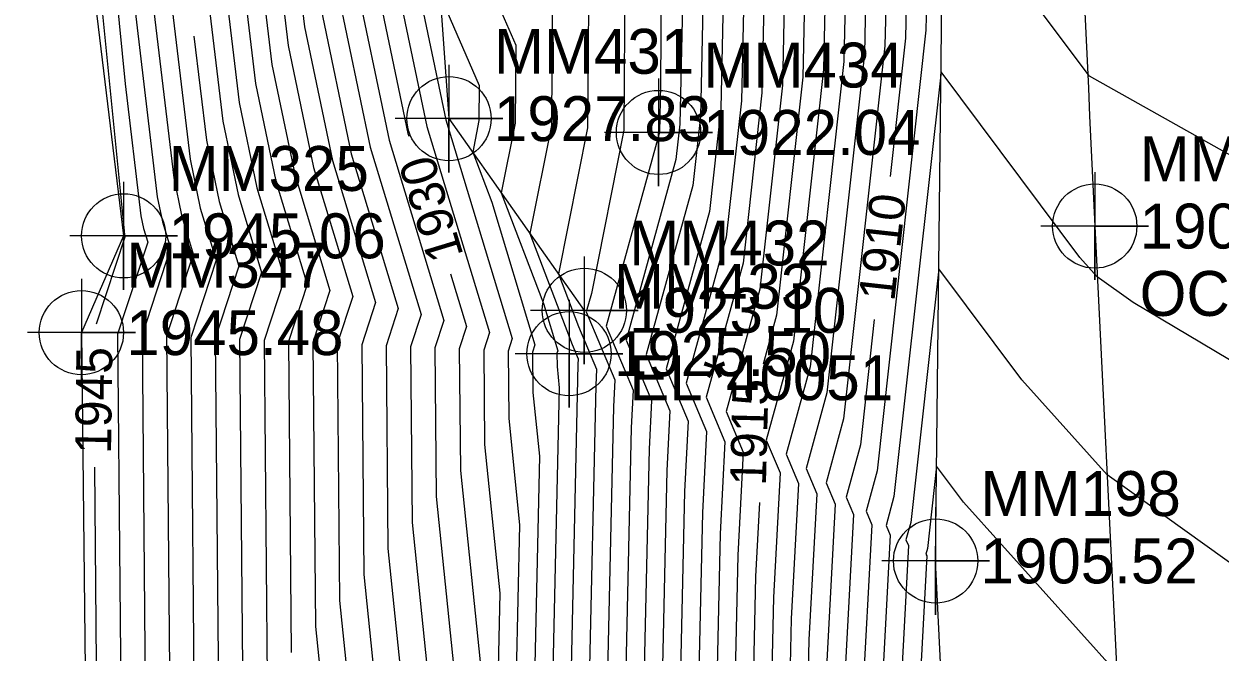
# Model space of a CAD drawing. Extents: x 1004378 to 1005103, y 553854 to 554288.
# Drawn here: x 1004943.2 to 1005009.8, y 554030.8 to 554065.8 of the extents above; entities that cross this region are included whole.
import ezdxf

# ---------------------------------------------------------------- set-up
doc = ezdxf.new("R2010")
doc.units = 0
for name, color, linetype in [('DTM Contours Major', 7, 'Continuous'), ('DTM Contours Major Text', 7, 'Continuous'), ('DTM Contours Minor', 7, 'Continuous'), ('Exist DTM Breakline', 7, 'Continuous'), ('Exist DTM Breakline Cogo Comment', 7, 'Continuous'), ('Exist DTM Breakline Cogo Elevation', 7, 'Continuous'), ('Exist DTM Breakline Cogo Number', 7, 'Continuous'), ('Exist DTM Breakline Cogo Point CELL', 7, 'Continuous'), ('Exist DTM Regular Point CELL', 7, 'Continuous'), ('Exist DTM Regular Point Cogo Elevation', 7, 'Continuous'), ('Exist DTM Regular Point Cogo Number', 7, 'Continuous'), ('Exist Roads EOP', 7, 'Continuous'), ('Exist Roads EOP Cogo Comment', 7, 'Continuous'), ('Exist Roads EOP Cogo Elevation', 7, 'Continuous'), ('Exist Roads EOP Cogo Number', 7, 'Continuous'), ('Exist Roads EOP Cogo Point CELL', 7, 'Continuous')]:
    doc.layers.add(name, color=color, linetype=linetype)

msp = doc.modelspace()

# ---------------------------------------------------------------- linework, layer by layer
at = {"layer": 'DTM Contours Major'}
for points in [[(1004974.291, 554156.941), (1004974.539, 554153.633), (1004973.275, 554148.595), (1004975.533, 554125.683), (1004973.303, 554118.045), (1004966.649, 554100.709), (1004964.833, 554091.127), (1004964.446, 554090.268), (1004962.705, 554079.148), (1004961.826, 554075.049), (1004962.449, 554069.829), (1004964.566, 554059.674), (1004964.614, 554059.515)], [(1005000.387, 554132.231), (1004993.714, 554134.749), (1004991.768, 554134.399), (1004990.994, 554131.312), (1004991.049, 554130.756), (1004984.364, 554107.86), (1004983.427, 554105.42), (1004981.8, 554096.829), (1004980.532, 554086.898), (1004982.359, 554084.869), (1004986.035, 554077.591), (1004986.969, 554072.114), (1004986.697, 554069.843), (1004986.544, 554062.802), (1004985.079, 554049.563), (1004984.328, 554046.826)], [(1004912.064, 554126.115), (1004911.158, 554121.47), (1004914.724, 554118.563), (1004927.833, 554107.862), (1004928.535, 554107.974), (1004932.097, 554104.869), (1004931.879, 554104.636), (1004950.839, 554094.361), (1004950.581, 554093.249), (1004946.204, 554080.072), (1004948.75, 554054.444), (1004948.799, 554054.036), (1004948.807, 554053.997), (1004948.82, 554053.955), (1004947.217, 554049.061)], [(1004962.871, 554103.868), (1004961.056, 554099.139), (1004960.026, 554093.701), (1004959.475, 554092.482), (1004958.495, 554086.221), (1004956.453, 554076.695), (1004957.899, 554064.565), (1004959.313, 554057.782), (1004961.493, 554050.599), (1004960.632, 554047.97), (1004960.758, 554033.678), (1004963.076, 554011.188), (1004962.949, 554005.526)], [(1004970.528, 554093.236), (1004969.641, 554088.552), (1004969.416, 554088.055), (1004967.45, 554075.492), (1004969.542, 554073.85), (1004972.596, 554066.826), (1004972.547, 554060.122), (1004971.354, 554054.113), (1004973.706, 554047.918), (1004974.042, 554047.122), (1004974.026, 554046.818), (1004973.213, 554010.493), (1004972.706, 553999.94), (1004972.315, 553996.671), (1004972.236, 553995.839)], [(1004974.172, 554084.471), (1004973.846, 554082.386), (1004977.708, 554079.356), (1004979.951, 554076.865), (1004980.929, 554074.931), (1004981.177, 554073.474), (1004981.105, 554072.871), (1004980.838, 554060.621), (1004980.413, 554056.78), (1004977.827, 554047.365), (1004979.146, 554044.236), (1004978.97, 554040.918), (1004978.353, 554013.324), (1004977.634, 553998.359), (1004977.079, 553993.724), (1004976.557, 553988.222)], [(1005051.433, 554076.836), (1005050.379, 554076.997), (1005049.638, 554077.419), (1005048.654, 554073.906), (1005043.562, 554064.845), (1005040.05, 554064.129), (1005027.148, 554065.55), (1005021.967, 554066.02), (1005015.22, 554068.538), (1005006.107, 554071.836), (1005002.083, 554074.095), (1005000.368, 554076.389), (1005000.016, 554076.907), (1004996.136, 554080.152), (1004993.696, 554082.636), (1004992.74, 554083.442), (1004991.884, 554081.943), (1004990.65, 554081.337), (1004990.87, 554080.789), (1004991.142, 554080.251), (1004992.761, 554070.753), (1004992.29, 554066.815), (1004992.25, 554064.983), (1004991.398, 554057.275)], [(1004952.659, 554065.091), (1004953.349, 554059.3), (1004954.06, 554055.889), (1004955.156, 554052.277), (1004953.842, 554048.264), (1004954.035, 554026.446), (1004955.827, 554009.057), (1004955.839, 554007.597), (1004955.608, 554000.346), (1004953.019, 553984.313), (1004948.054, 553966.564)], [(1004966.938, 554051.86), (1004967.829, 554048.921), (1004967.422, 554047.677), (1004967.482, 554040.91), (1004968.579, 554030.261), (1004968.073, 554007.661), (1004967.778, 554001.521), (1004967.551, 553999.619), (1004964.757, 553970.225), (1004964.471, 553967.778), (1004960.654, 553952.767)], [(1004990.518, 554049.324), (1004989.746, 554042.345), (1004988.945, 554039.431), (1004989.353, 554038.463), (1004988.859, 554029.118), (1004988.632, 554018.987), (1004987.49, 553995.198), (1004986.608, 553987.828), (1004985.684, 553978.101), (1004983.38, 553958.418), (1004981.497, 553951.011), (1004981.379, 553950.073)], [(1004947.118, 554041.088), (1004947.311, 554019.215), (1004947.454, 554017.827), (1004947.487, 554013.967), (1004946.931, 553996.538), (1004946.571, 553995.053), (1004931.009, 553978.241), (1004928.196, 553974.545), (1004916.189, 553970.124), (1004914.888, 553969.412), (1004912.358, 553969.149), (1004911.765, 553968.617), (1004911.067, 553969.318), (1004903.448, 553970.699)], [(1004984.132, 554039.131), (1004983.915, 554035.018), (1004983.493, 554016.156), (1004982.562, 553996.779), (1004981.844, 553990.776), (1004980.452, 553976.132), (1004978.652, 553960.758), (1004976.062, 553950.567), (1004975.294, 553944.427), (1004974.577, 553939.804)]]:
    msp.add_lwpolyline(points, dxfattribs=at)
at = {"layer": 'DTM Contours Minor'}
for points in [[(1004988.98, 554130.079), (1004982.889, 554109.218), (1004981.19, 554104.792), (1004978.237, 554089.207), (1004977.787, 554085.675), (1004981.396, 554081.667), (1004983.993, 554076.527), (1004984.652, 554072.658), (1004984.46, 554071.054), (1004984.262, 554061.93), (1004983.213, 554052.45), (1004981.163, 554044.985), (1004982.208, 554042.504), (1004981.937, 554037.378), (1004981.437, 554015.023)], [(1004990.014, 554130.417), (1004983.627, 554108.539), (1004982.309, 554105.106), (1004980.019, 554093.018), (1004979.159, 554086.286), (1004981.877, 554083.268), (1004985.014, 554077.059), (1004985.811, 554072.386), (1004985.579, 554070.449), (1004985.403, 554062.366), (1004984.146, 554051.006), (1004982.275, 554044.191), (1004983.229, 554041.926), (1004982.926, 554036.198), (1004982.465, 554015.589)], [(1004986.911, 554129.403), (1004981.414, 554110.576), (1004978.953, 554104.164), (1004975.41, 554085.463), (1004975.381, 554085.398), (1004975.125, 554083.765), (1004976.951, 554082.333), (1004980.433, 554078.466), (1004981.95, 554075.463), (1004982.335, 554073.202), (1004982.223, 554072.265), (1004981.979, 554061.057), (1004981.346, 554055.337), (1004978.939, 554046.571), (1004980.166, 554043.658), (1004979.959, 554039.738), (1004979.381, 554013.891)], [(1004987.946, 554129.741), (1004982.152, 554109.897), (1004980.072, 554104.478), (1004976.456, 554085.395), (1004976.414, 554085.064), (1004980.914, 554080.067), (1004982.971, 554075.995), (1004983.494, 554072.93), (1004983.342, 554071.66), (1004983.12, 554061.493), (1004982.279, 554053.893), (1004980.051, 554045.778), (1004981.187, 554043.081), (1004980.948, 554038.558), (1004980.409, 554014.457)], [(1004983.808, 554128.388), (1004979.202, 554112.613), (1004975.597, 554103.222), (1004972.525, 554087.008), (1004972.399, 554086.726), (1004971.288, 554079.628), (1004978.513, 554073.96), (1004978.694, 554073.543), (1004978.613, 554062.384), (1004978.555, 554059.749), (1004978.546, 554059.667), (1004975.604, 554048.951), (1004977.104, 554045.39), (1004976.992, 554043.278), (1004976.297, 554012.192)], [(1004984.843, 554128.727), (1004979.94, 554111.934), (1004976.716, 554103.536), (1004973.487, 554086.493), (1004973.393, 554086.284), (1004972.567, 554081.007), (1004978.466, 554076.38), (1004979.47, 554075.265), (1004979.907, 554074.399), (1004980.018, 554073.747), (1004979.986, 554073.476), (1004979.696, 554060.185), (1004979.479, 554058.224), (1004976.716, 554048.158), (1004978.125, 554044.813), (1004977.981, 554042.098), (1004977.325, 554012.758)], [(1004981.739, 554127.712), (1004977.727, 554113.971), (1004973.36, 554102.594), (1004970.602, 554088.037), (1004970.41, 554087.612), (1004968.729, 554076.871), (1004972.533, 554073.887), (1004974.629, 554069.065), (1004974.562, 554059.989), (1004972.947, 554051.855), (1004974.061, 554048.923), (1004975.063, 554046.545), (1004975.015, 554045.638), (1004974.241, 554011.059)], [(1004982.774, 554128.05), (1004978.465, 554113.292), (1004974.479, 554102.908), (1004971.564, 554087.523), (1004971.404, 554087.169), (1004970.008, 554078.249), (1004975.523, 554073.924), (1004976.661, 554071.304), (1004976.578, 554059.857), (1004974.774, 554050.773), (1004974.492, 554049.745), (1004976.083, 554045.967), (1004976.003, 554044.458), (1004975.269, 554011.625)], [(1004979.671, 554127.036), (1004976.253, 554115.329), (1004971.123, 554101.966), (1004968.679, 554089.067), (1004968.422, 554088.497), (1004966.171, 554074.113), (1004966.552, 554073.814), (1004970.563, 554064.587), (1004970.531, 554060.254), (1004969.76, 554056.371), (1004972.101, 554050.208), (1004972.899, 554047.579), (1004972.854, 554047.442), (1004972.86, 554046.695), (1004972.981, 554045.52), (1004972.185, 554009.926)], [(1004977.602, 554126.359), (1004974.778, 554116.687), (1004968.886, 554101.338), (1004966.756, 554090.097), (1004966.434, 554089.383), (1004964.389, 554076.319), (1004963.976, 554074.391), (1004964.268, 554071.934), (1004966.667, 554060.431), (1004970.364, 554048.25), (1004970.138, 554047.559), (1004970.171, 554043.802), (1004970.78, 554037.89), (1004970.129, 554008.794)], [(1004978.636, 554126.697), (1004975.515, 554116.008), (1004970.004, 554101.652), (1004967.718, 554089.582), (1004967.428, 554088.94), (1004965.231, 554074.905), (1004965.05, 554074.061), (1004965.178, 554072.987), (1004966.353, 554067.357), (1004968.53, 554062.348), (1004968.516, 554060.387), (1004968.167, 554058.63), (1004969.226, 554055.84), (1004971.631, 554047.915), (1004971.496, 554047.501), (1004971.516, 554045.249), (1004971.881, 554041.705), (1004971.157, 554009.36)], [(1005041.535, 554126.294), (1005027.186, 554113.002), (1005025.646, 554112.306), (1005019.626, 554109.515), (1005013.669, 554108.071), (1005006.504, 554108.468), (1005001.004, 554108.005), (1004994.526, 554114.001), (1004990.716, 554115.591), (1004987.329, 554111.605), (1004985.839, 554106.502), (1004985.665, 554106.048), (1004985.362, 554104.451), (1004983.277, 554088.12), (1004983.322, 554088.07), (1004988.078, 554078.655), (1004989.286, 554071.569), (1004988.935, 554068.632), (1004988.827, 554063.674), (1004986.946, 554046.675), (1004985.61, 554041.811), (1004986.291, 554040.195), (1004985.892, 554032.658), (1004985.548, 554017.288)], [(1004976.568, 554126.021), (1004974.041, 554117.366), (1004967.767, 554101.024), (1004965.795, 554090.612), (1004965.44, 554089.826), (1004963.547, 554077.734), (1004962.901, 554074.72), (1004963.358, 554070.882), (1004965.617, 554060.053), (1004969.097, 554048.586), (1004968.78, 554047.618), (1004968.826, 554042.356), (1004969.679, 554034.076), (1004969.101, 554008.227)], [(1004935.046, 554124.799), (1004945.367, 554115.802), (1004966.063, 554119.983), (1004957.7, 554098.197), (1004957.141, 554095.246), (1004956.493, 554093.81), (1004955.969, 554090.464), (1004953.229, 554077.683), (1004955.169, 554061.406), (1004956.161, 554056.646), (1004957.691, 554051.606), (1004956.558, 554048.146), (1004956.724, 554029.339)], [(1004973.465, 554125.006), (1004971.828, 554119.403), (1004964.412, 554100.081), (1004962.91, 554092.157), (1004962.458, 554091.154), (1004961.021, 554081.977), (1004959.677, 554075.708), (1004960.629, 554067.723), (1004962.465, 554058.917), (1004965.295, 554049.592), (1004964.706, 554047.794), (1004964.792, 554038.017), (1004966.378, 554022.632)], [(1004974.499, 554125.345), (1004972.566, 554118.724), (1004965.53, 554100.395), (1004963.872, 554091.642), (1004963.452, 554090.711), (1004961.863, 554080.563), (1004960.752, 554075.378), (1004961.539, 554068.776), (1004963.515, 554059.296), (1004966.562, 554049.257), (1004966.064, 554047.735), (1004966.137, 554039.463), (1004967.478, 554026.447)], [(1004989.854, 554123.457), (1004985.101, 554107.181), (1004984.546, 554105.734), (1004983.581, 554100.64), (1004981.905, 554087.509), (1004982.841, 554086.469), (1004987.056, 554078.123), (1004988.127, 554071.842), (1004987.816, 554069.238), (1004987.685, 554063.238), (1004986.012, 554048.119), (1004984.498, 554042.605), (1004985.27, 554040.772), (1004984.903, 554033.838), (1004984.52, 554016.722)], [(1004919.981, 554122.802), (1004927.333, 554116.8), (1004932.255, 554117.588), (1004952.404, 554100.025), (1004955.66, 554100.683), (1004954.344, 554097.255), (1004954.256, 554096.791), (1004953.511, 554095.139), (1004953.443, 554094.708), (1004950.005, 554078.671), (1004952.439, 554058.248), (1004953.009, 554055.511), (1004953.889, 554052.612), (1004952.484, 554048.322), (1004952.69, 554025)], [(1004968.142, 554122.798), (1004958.819, 554098.511), (1004958.102, 554094.731), (1004957.487, 554093.368), (1004956.811, 554089.05), (1004954.303, 554077.354), (1004956.079, 554062.459), (1004957.212, 554057.025), (1004958.958, 554051.27), (1004957.916, 554048.088), (1004958.069, 554030.785)], [(1004934.115, 554122.395), (1004947.713, 554110.543), (1004962.595, 554113.55), (1004956.581, 554097.883), (1004956.179, 554095.761), (1004955.499, 554094.253), (1004955.127, 554091.879), (1004952.154, 554078.013), (1004954.259, 554060.353), (1004955.111, 554056.268), (1004956.424, 554051.941), (1004955.2, 554048.205), (1004955.379, 554027.893)], [(1004968.879, 554122.119), (1004959.937, 554098.825), (1004959.064, 554094.216), (1004958.481, 554092.925), (1004957.653, 554087.635), (1004955.378, 554077.025), (1004956.989, 554063.512), (1004958.262, 554057.403), (1004960.226, 554050.935), (1004959.274, 554048.029), (1004959.413, 554032.232), (1004961.975, 554007.374)], [(1004918.667, 554121.742), (1004927.458, 554114.566), (1004931.325, 554115.185), (1004950.953, 554098.075), (1004949.754, 554096.79), (1004952.721, 554095.183), (1004949.04, 554079.301), (1004948.941, 554079.002), (1004948.999, 554078.42), (1004951.529, 554057.195), (1004951.959, 554055.132), (1004952.622, 554052.948), (1004951.126, 554048.381), (1004951.345, 554023.554)], [(1004970.354, 554120.761), (1004962.174, 554099.453), (1004960.987, 554093.186), (1004960.469, 554092.039), (1004959.337, 554084.806), (1004957.527, 554076.366), (1004958.809, 554065.617), (1004960.364, 554058.16), (1004962.76, 554050.264), (1004961.99, 554047.911), (1004962.103, 554035.124), (1004964.176, 554015.003)], [(1004917.352, 554120.683), (1004927.583, 554112.331), (1004930.395, 554112.781), (1004944.668, 554100.34), (1004943.796, 554099.406), (1004952.093, 554094.909), (1004949.554, 554083.951), (1004948.029, 554079.359), (1004948.916, 554070.428), (1004950.619, 554056.142), (1004950.908, 554054.754), (1004951.354, 554053.283), (1004949.768, 554048.44), (1004950.001, 554022.107)], [(1004971.091, 554120.082), (1004963.293, 554099.767), (1004961.949, 554092.671), (1004961.463, 554091.597), (1004960.179, 554083.392), (1004958.602, 554076.037), (1004959.719, 554066.67), (1004961.414, 554058.539), (1004964.027, 554049.928), (1004963.348, 554047.853), (1004963.448, 554036.571), (1004965.277, 554018.817)], [(1004916.038, 554119.623), (1004927.708, 554110.097), (1004929.465, 554110.378), (1004938.382, 554102.604), (1004937.837, 554102.021), (1004951.466, 554094.635), (1004950.068, 554088.6), (1004947.116, 554079.715), (1004948.833, 554062.436), (1004949.709, 554055.089), (1004949.858, 554054.375), (1004950.087, 554053.619), (1004948.41, 554048.498), (1004948.656, 554020.661)], [(1005010.132, 554096.182), (1005001.278, 554096.56), (1004999.274, 554098.601), (1004990.276, 554106.187), (1004990.27, 554106.177), (1004986.161, 554098.879), (1004984.854, 554088.057), (1004985.769, 554085.78), (1004989.099, 554079.187), (1004990.444, 554071.297), (1004990.053, 554068.027), (1004989.968, 554064.111), (1004987.879, 554045.232), (1004986.722, 554041.018), (1004987.312, 554039.617), (1004986.881, 554031.478), (1004986.576, 554017.855)], [(1005014.682, 554081.634), (1005004.85, 554085.192), (1005001.681, 554085.328), (1004996.485, 554090.618), (1004991.508, 554094.815), (1004987.057, 554087.013), (1004986.86, 554086.916), (1004988.319, 554083.285), (1004990.12, 554079.719), (1004991.603, 554071.025), (1004991.172, 554067.421), (1004991.109, 554064.547), (1004988.812, 554043.788), (1004987.834, 554040.225), (1004988.333, 554039.04), (1004987.87, 554030.298)], [(1005050.437, 554057.486), (1005048.879, 554054.931), (1005048.518, 554054.142), (1005043.793, 554047.065), (1005040.855, 554048.876), (1005027.803, 554050.713), (1005026.234, 554051.882), (1005016.31, 554055.236), (1005015.759, 554055.441), (1005015.604, 554055.497), (1005002.486, 554062.863), (1004996.894, 554070.341), (1004995.745, 554072.029), (1004993.918, 554073.557), (1004993.443, 554073.279), (1004993.92, 554070.481), (1004993.409, 554066.21), (1004993.392, 554065.419), (1004990.679, 554040.901), (1004990.057, 554038.638), (1004990.374, 554037.886), (1004989.848, 554027.938)], [(1005049.523, 554042.345), (1005045.034, 554033.434), (1005043.176, 554030.651), (1005034.444, 554036.034), (1005028.658, 554036.849), (1005022.704, 554041.282), (1005016.415, 554043.408), (1005004.921, 554050.257), (1005002.926, 554051.684), (1005001.954, 554052.767), (1004994.229, 554063.106), (1004991.612, 554039.458), (1004991.169, 554037.845), (1004991.395, 554037.308), (1004990.837, 554026.758)], [(1005019.174, 554030.683), (1005017.072, 554031.393), (1005013.231, 554033.682), (1005003.473, 554040.664), (1004998.719, 554045.96), (1004994.107, 554052.132), (1004992.545, 554038.014), (1004992.281, 554037.051), (1004992.416, 554036.731), (1004991.826, 554025.578)], [(1005004.02, 554029.644), (1004995.485, 554039.153), (1004993.986, 554041.159), (1004993.479, 554036.571), (1004993.393, 554036.258), (1004993.436, 554036.154), (1004992.815, 554024.398)]]:
    msp.add_lwpolyline(points, dxfattribs=at)
at = {"layer": 'Exist DTM Breakline'}
for points in [[(1004987.71, 553883.194), (1004993.763, 553908.865), (1004995.956, 553952.192), (1004996.06, 553992.449), (1004993.928, 554035.876), (1004994.309, 554070.389), (1004993.033, 554080.737), (1004990.275, 554106.198), (1004991.435, 554130.882), (1004994.664, 554165.005), (1004997.714, 554181.706), (1005005.106, 554206.988)], [(1004908.599, 554113.626), (1004928.542, 554104.358), (1004950.697, 554094.299), (1004945.541, 554080.331), (1004948.745, 554053.974), (1004946.395, 554048.586), (1004946.774, 554014.511), (1004946.946, 553994.845), (1004942.426, 553964.624), (1004933.56, 553959.38), (1004919.92, 553960.138), (1004910.869, 553961.543), (1004894.885, 553951.978), (1004894.101, 553924.52), (1004896.848, 553886.739), (1004896.026, 553883.694)], [(1004983.346, 554088.15), (1004976.272, 554085.001), (1004965.886, 554073.806), (1004966.849, 554060.497), (1004974.38, 554049.825)]]:
    msp.add_lwpolyline(points, dxfattribs=at)
at = {"layer": 'Exist DTM Breakline Cogo Point CELL'}
for points in [[(1004966.849, 554063.497), (1004966.849, 554057.497), (1004966.849, 554060.497), (1004969.849, 554060.497), (1004963.849, 554060.497)], [(1004948.745, 554056.974), (1004948.745, 554050.974), (1004948.745, 554053.974), (1004951.745, 554053.974), (1004945.745, 554053.974)], [(1004974.38, 554052.825), (1004974.38, 554046.825), (1004974.38, 554049.825), (1004977.38, 554049.825), (1004971.38, 554049.825)], [(1004946.395, 554051.586), (1004946.395, 554045.586), (1004946.395, 554048.586), (1004949.395, 554048.586), (1004943.395, 554048.586)], [(1004993.928, 554038.876), (1004993.928, 554032.876), (1004993.928, 554035.876), (1004996.928, 554035.876), (1004990.928, 554035.876)]]:
    msp.add_lwpolyline(points, dxfattribs=at)
for centre in [(1004966.849, 554060.497), (1004948.745, 554053.974), (1004974.38, 554049.825), (1004946.395, 554048.586), (1004993.928, 554035.876)]:
    msp.add_circle(centre, 2.344, dxfattribs=at)
at = {"layer": 'Exist DTM Regular Point CELL'}
for points in [[(1004978.506, 554062.73), (1004978.506, 554056.73), (1004978.506, 554059.73), (1004981.506, 554059.73), (1004975.506, 554059.73)], [(1004973.528, 554050.413), (1004973.528, 554044.413), (1004973.528, 554047.413), (1004976.528, 554047.413), (1004970.528, 554047.413)]]:
    msp.add_lwpolyline(points, dxfattribs=at)
for centre in [(1004978.506, 554059.73), (1004973.528, 554047.413)]:
    msp.add_circle(centre, 2.344, dxfattribs=at)
at = {"layer": 'Exist Roads EOP'}
msp.add_line((1005002.785, 554054.517), (1005004.922, 554011.456), dxfattribs=at)
msp.add_spline([(1005026.381, 554243.671), (1005017.049, 554225.785), (1005004.478, 554185.698), (1005001.445, 554147.868), (1005001.025, 554103.612), (1005002.785, 554054.517)], degree=3, dxfattribs=at)
at = {"layer": 'Exist Roads EOP Cogo Point CELL'}
msp.add_lwpolyline([(1005002.785, 554057.517), (1005002.785, 554051.517), (1005002.785, 554054.517), (1005005.785, 554054.517), (1004999.785, 554054.517)], dxfattribs=at)
msp.add_circle((1005002.785, 554054.517), 2.344, dxfattribs=at)

# ---------------------------------------------------------------- texts
at = {"layer": 'DTM Contours Major Text'}
for s, rotation, p in [('1930', 106.88284, (1004967.668, 554052.896)), ('1910', 83.68616, (1004991.63, 554050.286)), ('1945', 89.28914, (1004948.042, 554041.823)), ('1915', 88.54372, (1004984.485, 554040.042))]:
    msp.add_text(s, height=2, rotation=rotation, dxfattribs=at).set_placement(p)
at = {"layer": 'Exist DTM Breakline Cogo Comment'}
msp.add_text('EL*40051', height=2.5, dxfattribs=at).set_placement((1004976.88, 554044.825))
at = {"layer": 'Exist DTM Breakline Cogo Elevation'}
for s, p in [('1927.83', (1004969.349, 554059.247)), ('1945.06', (1004951.245, 554052.724)), ('1923.10', (1004976.88, 554048.575)), ('1945.48', (1004948.895, 554047.336)), ('1905.52', (1004996.428, 554034.626))]:
    msp.add_text(s, height=2.5, dxfattribs=at).set_placement(p)
at = {"layer": 'Exist DTM Breakline Cogo Number'}
for s, p in [('MM431', (1004969.349, 554062.997)), ('MM325', (1004951.245, 554056.474)), ('MM432', (1004976.88, 554052.325)), ('MM347', (1004948.895, 554051.086)), ('MM198', (1004996.428, 554038.376))]:
    msp.add_text(s, height=2.5, dxfattribs=at).set_placement(p)
at = {"layer": 'Exist DTM Regular Point Cogo Elevation'}
for s, p in [('1922.04', (1004981.006, 554058.48)), ('1925.50', (1004976.028, 554046.163))]:
    msp.add_text(s, height=2.5, dxfattribs=at).set_placement(p)
at = {"layer": 'Exist DTM Regular Point Cogo Number'}
for s, p in [('MM434', (1004981.006, 554062.23)), ('MM433', (1004976.028, 554049.913))]:
    msp.add_text(s, height=2.5, dxfattribs=at).set_placement(p)
at = {"layer": 'Exist Roads EOP Cogo Comment'}
msp.add_text('OC*30011', height=2.5, dxfattribs=at).set_placement((1005005.285, 554049.517))
at = {"layer": 'Exist Roads EOP Cogo Elevation'}
msp.add_text('1908.26', height=2.5, dxfattribs=at).set_placement((1005005.285, 554053.267))
at = {"layer": 'Exist Roads EOP Cogo Number'}
msp.add_text('MM153', height=2.5, dxfattribs=at).set_placement((1005005.285, 554057.017))

doc.saveas('drawing.dxf')
